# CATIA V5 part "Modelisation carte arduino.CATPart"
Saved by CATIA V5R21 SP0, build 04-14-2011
Part number: Modélisation Carte Arduino
Bounding box of the stored display mesh (mm): x 0 to 106.6, y 0 to 53.3, z 0 to 13
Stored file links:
  C:\Users\2027.DESARCY-LEMIE30\Desktop\Assemblage26.05\Modelisation carte arduino.CATPart
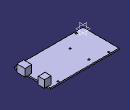
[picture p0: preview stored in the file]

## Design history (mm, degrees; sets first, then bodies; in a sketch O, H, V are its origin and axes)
Body1 (main body)
  Sketch1 on xy-plane, origin (0, 0, 0), H (1, 0, 0), V (0, 1, 0)
    line L1 (0, 53.3) -> (101.6, 53.3)
    line L2 (101.6, 53.3) -> (101.6, 0)
    line L3 (101.6, 0) -> (0, 0)
    line L4 (0, 0) -> (0, 53.3)
    point P4 (0, 0)
    length L3 = 101.6
    length L2 = 53.3
    horizontal: L1 H, L3 H
    vertical: L2 V, L4 V
    coincidence: P4 O
  Pad1: profile Sketch1, direction (0, 0, 1), length 2
  Sketch2 on face of Pad1 from Sketch1.L2, origin (101.6, 0, 0), H (0, 1, 0), V (0, 0, 1)
    line L1 (8.8, 13) -> (20.8, 13)
    line L2 (20.8, 13) -> (20.8, 2)
    line L3 (20.8, 2) -> (8.8, 2)
    line L4 (8.8, 2) -> (8.8, 13)
    reference projected line E1 (0, 2) -> (53.3, 2) from edge [face of Pad1 from Sketch1.L2 | end face of Pad1]
    line L5 (40.5, 13) -> (49.5, 13)
    line L6 (49.5, 13) -> (49.5, 2)
    line L7 (49.5, 2) -> (40.5, 2)
    line L8 (40.5, 2) -> (40.5, 13)
    reference projected line E2 (0, 2) -> (53.3, 2) from edge [face of Pad1 from Sketch1.L2 | end face of Pad1]
    distance L4 V = 8.8
    length L1 = 12
    length L2 = 11
    distance L2 L8 = 19.7
    length L5 = 9
    length L8 = 11
    horizontal: L1 H, L3 H, L5 H, L7 H
    vertical: L2 V, L4 V, L6 V, L8 V
    coincidence: L3 E1, E2 L7
  Pad2: profile Sketch2, direction (1, 0, 0), length 5, opposite side length 5
  Sketch3 on xy-plane, origin (0, 0, 0), H (1, 0, 0), V (0, 1, 0)
    circle A1 centre (87.6, 2.5) radius 1.3
    point P1 (87.6, 2.5)
    circle A2 centre (12.7, 2.5) radius 1.3
    point P2 (12.7, 2.5)
    circle A3 centre (87.6, 50.7) radius 1.3
    point P3 (87.6, 50.7)
    circle A4 centre (12.7, 50.7) radius 1.3
    point P4 (12.7, 50.7)
    reference projected line E1 (101.6, 0) -> (101.6, 53.3) from edge [face of Pad1 from Sketch1.L2 | end face of Pad1]
    circle A5 centre (36.8, 17.7) radius 1.3
    point P5 (36.8, 17.7)
    circle A6 centre (36.8, 45.6) radius 1.3
    point P6 (36.8, 45.6)
    reference projected line E2 (0, 0) -> (101.6, 0) from edge [face of Pad1 from Sketch1.L3 | end face of Pad1]
    construction line L1 (104.2729, 2.5) -> (-3.8985, 2.5)
    construction line L2 (36.8, 7.0859) -> (36.8, 48.7575)
    construction line L3 (110.6573, 50.7) -> (14.6616, 50.7)
    construction line L4 (87.6, -3.0536) -> (87.6, 62.1687)
    axis line L5 (12.7, -7.199) -> (12.7, 65.513)
    radius A4 = 1.3
    radius A3 = 1.3
    radius A1 = 1.3
    radius A2 = 1.3
    distance P1 E1 = 14
    radius A5 = 1.3
    radius A6 = 1.3
    distance P5 P2 V = 15.2
    distance P2 E2 = 2.5
    distance P5 P2 H = 24.1
    distance P2 P1 H = 74.9
    distance P5 P6 = 27.9
    distance P6 P4 V = 5.1
    horizontal: L1 H, L3 H
    coincidence: P2 L1, P1 L1, L2 P5, P6 L2, P4 L3, P3 L3, P3 L4, L4 P1, P4 L5, L5 P2
    vertical: L2 V, L4 V, L5 V
  Pocket1: profile Sketch3, direction (0, 0, -1), through (limit type 3)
